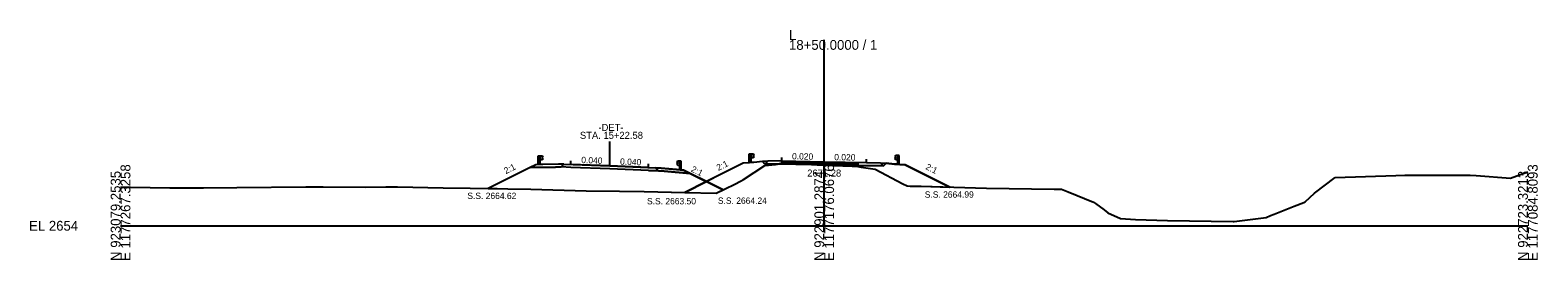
# Model space of a CAD drawing. Extents: x -26 to 1403, y -10 to 9563.
# Drawn here: x -25.7 to 402.8, y 8490.3 to 8555.6 of the extents above; entities that cross this region are included whole.
import ezdxf

# ---------------------------------------------------------------- set-up
doc = ezdxf.new("R2010")
doc.units = 0
for name, color, linetype in [('Exist Cross Section Cell', 7, 'Continuous'), ('Exist XS Center Line Elevation Label', 7, 'Continuous'), ('Exist XS Ground Line', 7, 'Continuous'), ('Prop XS Dump Level', 7, 'Continuous'), ('Prop XS Earthwork Shape', 7, 'Continuous'), ('Prop XS EOT Tick Mark', 7, 'Continuous'), ('Prop XS Finish Grade', 7, 'Continuous'), ('Prop XS Finish Grade Earthwork', 7, 'Continuous'), ('Prop XS Finish Grade Paved Shoulder', 7, 'Continuous'), ('Prop XS Finish Grade Pavement', 7, 'Continuous'), ('Prop XS Guardrail', 7, 'Continuous'), ('Prop XS Pvmt Edge Slope', 7, 'Continuous'), ('Prop XS SE Text', 7, 'Continuous'), ('Prop XS Shoulder Borrow Shape', 7, 'Continuous'), ('Prop XS Side Slope Text', 7, 'Continuous'), ('Prop XS SS Elevation Text', 7, 'Continuous'), ('Prop XS Subgrade Earthwork', 7, 'Continuous'), ('Prop XS Vertical Lines', 7, 'Continuous'), ('Prop XS Wedging', 7, 'Continuous')]:
    doc.layers.add(name, color=color, linetype=linetype)

msp = doc.modelspace()

# ---------------------------------------------------------------- linework, layer by layer
at = {"layer": 'Exist Cross Section Cell'}
for p, q in [((200, 8500), (200, 8552.84)), ((0, 8500), (200, 8500)), ((200, 8500), (400, 8500))]:
    msp.add_line(p, q, dxfattribs=at)
at = {"layer": 'Exist XS Ground Line'}
for p, q in [((177.02, 8513.16), (183.08, 8517.11)), ((183.08, 8517.11), (186.16, 8517.47)), ((186.16, 8517.47), (187.36, 8517.61)), ((187.36, 8517.61), (196.36, 8517.4)), ((196.36, 8517.4), (197.99, 8517.36)), ((197.99, 8517.36), (200, 8517.28)), ((200, 8517.28), (207.95, 8516.94)), ((207.95, 8516.94), (209.54, 8516.86)), ((209.54, 8516.86), (210.55, 8516.7)), ((210.55, 8516.7), (214.49, 8516.09)), ((214.49, 8516.09), (222.34, 8511.97)), ((395.04, 8513.57), (400, 8515.31)), ((0, 8510.95), (2.86, 8510.96)), ((2.86, 8510.96), (14, 8510.78)), ((14, 8510.78), (20.88, 8510.77)), ((20.88, 8510.77), (23.56, 8510.77)), ((23.56, 8510.77), (33.09, 8510.85)), ((33.09, 8510.85), (52.68, 8511.08)), ((52.68, 8511.08), (57.59, 8511.05)), ((57.59, 8511.05), (69.68, 8511.02)), ((69.68, 8511.02), (75.4, 8511.08)), ((75.4, 8511.08), (78.69, 8511.05)), ((78.69, 8511.05), (91.74, 8510.78)), ((91.74, 8510.78), (107.09, 8510.59)), ((172.06, 8510.61), (174.41, 8511.77)), ((174.41, 8511.77), (176.36, 8512.74)), ((176.36, 8512.74), (177.02, 8513.16)), ((222.34, 8511.97), (223.55, 8511.34)), ((223.55, 8511.34), (224.46, 8511.3)), ((224.46, 8511.3), (227.58, 8511.24)), ((227.58, 8511.24), (246.16, 8510.67)), ((246.16, 8510.67), (265.41, 8510.43)), ((339.37, 8509.28), (345.21, 8513.7)), ((345.21, 8513.7), (362.5, 8514.26)), ((362.5, 8514.26), (365, 8514.4)), ((365, 8514.4), (366.49, 8514.42)), ((366.49, 8514.42), (368.44, 8514.4)), ((368.44, 8514.4), (383.21, 8514.39)), ((383.21, 8514.39), (383.56, 8514.41)), ((383.56, 8514.41), (385.3, 8514.27)), ((385.3, 8514.27), (395.04, 8513.57)), ((107.09, 8510.59), (110.11, 8510.53)), ((110.11, 8510.53), (116.65, 8510.37)), ((116.65, 8510.37), (132.38, 8509.95)), ((132.38, 8509.95), (141.79, 8509.85)), ((141.79, 8509.85), (148.87, 8509.72)), ((148.87, 8509.72), (160.51, 8509.5)), ((160.51, 8509.5), (169.34, 8509.29)), ((169.34, 8509.29), (172.06, 8510.61)), ((265.41, 8510.43), (267.42, 8510.41)), ((267.42, 8510.41), (269.38, 8509.61)), ((269.38, 8509.61), (276.55, 8506.7)), ((276.55, 8506.7), (277.08, 8506.34)), ((333.6, 8505.59), (336.33, 8506.66)), ((336.33, 8506.66), (336.67, 8506.85)), ((336.67, 8506.85), (339.37, 8509.28)), ((277.08, 8506.34), (279.58, 8504.49)), ((279.58, 8504.49), (280.64, 8503.71)), ((280.64, 8503.71), (284.18, 8502.04)), ((316.55, 8501.23), (325.62, 8502.34)), ((325.62, 8502.34), (326.88, 8502.92)), ((326.88, 8502.92), (327.85, 8503.29)), ((327.85, 8503.29), (333.6, 8505.59)), ((284.18, 8502.04), (288.48, 8501.79)), ((288.48, 8501.79), (297.54, 8501.54)), ((297.54, 8501.54), (316.22, 8501.22)), ((316.22, 8501.22), (316.55, 8501.23))]:
    msp.add_line(p, q, dxfattribs=at)
at = {"layer": 'Prop XS Dump Level'}
for p, q in [((126.02, 8517.53), (139.03, 8517.01)), ((139.03, 8517.01), (128.02, 8517.45)), ((150.04, 8516.58), (139.03, 8517.01)), ((139.03, 8517.01), (152.04, 8516.5)), ((188, 8518.44), (200, 8518.2)), ((200, 8518.2), (212, 8517.96))]:
    msp.add_line(p, q, dxfattribs=at)
at = {"layer": 'Prop XS Earthwork Shape'}
for p, q in [((116.38, 8516.55), (104.51, 8510.62)), ((123.65, 8516.7), (116.38, 8516.55)), ((125.22, 8516.73), (123.65, 8516.7)), ((128.02, 8516.62), (125.22, 8516.73)), ((139.03, 8516.18), (128.02, 8516.62)), ((150.04, 8515.74), (139.03, 8516.18)), ((152.91, 8515.63), (150.04, 8515.74)), ((154.52, 8515.5), (152.91, 8515.63)), ((161.95, 8514.9), (154.52, 8515.5)), ((177, 8517.8), (166.58, 8512.59)), ((177.02, 8513.16), (183.08, 8517.11)), ((182.43, 8518.24), (180, 8518.04)), ((183.15, 8517.51), (182.43, 8518.24)), ((183.08, 8517.11), (186.16, 8517.47)), ((187.21, 8517.59), (183.15, 8517.51)), ((186.16, 8517.47), (187.21, 8517.59)), ((187.36, 8517.61), (187.21, 8517.59)), ((187.21, 8517.59), (187.69, 8517.6)), ((187.69, 8517.6), (187.36, 8517.61)), ((188, 8517.61), (187.69, 8517.6)), ((187.69, 8517.6), (188, 8517.6)), ((188, 8517.6), (188, 8517.61)), ((216.85, 8517.03), (209.54, 8517.18)), ((209.54, 8517.18), (209.54, 8516.86)), ((209.54, 8516.86), (210.55, 8516.7)), ((210.55, 8516.7), (214.49, 8516.09)), ((214.49, 8516.09), (222.34, 8511.97)), ((217.57, 8517.76), (216.85, 8517.03)), ((220, 8517.56), (217.57, 8517.76)), ((220.82, 8517.5), (220, 8517.56)), ((235.67, 8510.99), (223, 8517.32)), ((160.39, 8509.5), (166.58, 8512.59)), ((166.58, 8512.59), (160.39, 8509.5)), ((166.58, 8512.59), (160.39, 8509.5)), ((166.58, 8512.59), (161.95, 8514.9)), ((171.29, 8510.24), (166.58, 8512.59)), ((171.29, 8510.24), (166.58, 8512.59)), ((166.58, 8512.59), (171.29, 8510.24)), ((172.06, 8510.61), (174.41, 8511.77)), ((174.41, 8511.77), (176.36, 8512.74)), ((176.36, 8512.74), (177.02, 8513.16)), ((222.34, 8511.97), (223.55, 8511.34)), ((223.55, 8511.34), (224.46, 8511.3)), ((224.46, 8511.3), (227.58, 8511.24)), ((227.58, 8511.24), (235.67, 8510.99)), ((104.51, 8510.62), (107.09, 8510.59)), ((107.09, 8510.59), (110.11, 8510.53)), ((110.11, 8510.53), (116.65, 8510.37)), ((116.65, 8510.37), (132.38, 8509.95)), ((132.38, 8509.95), (141.79, 8509.85)), ((141.79, 8509.85), (148.87, 8509.72)), ((148.87, 8509.72), (160.39, 8509.5)), ((160.39, 8509.5), (160.51, 8509.5)), ((160.39, 8509.5), (160.51, 8509.5)), ((160.51, 8509.5), (169.34, 8509.29)), ((160.51, 8509.5), (169.34, 8509.29)), ((169.34, 8509.29), (171.29, 8510.24)), ((169.34, 8509.29), (171.29, 8510.24)), ((171.29, 8510.24), (172.06, 8510.61))]:
    msp.add_line(p, q, dxfattribs=at)
for points in [[(180, 8518.04), (179.18, 8517.98), (178.68, 8517.94), (177, 8517.8)], [(223, 8517.32), (221.32, 8517.46), (220.82, 8517.5)]]:
    msp.add_lwpolyline(points, dxfattribs=at)
at = {"layer": 'Prop XS EOT Tick Mark'}
for p, q in [((188, 8518.44), (188, 8519.44)), ((128.02, 8517.45), (128.02, 8518.45)), ((150.04, 8516.58), (150.04, 8517.58)), ((212, 8517.96), (212, 8518.96))]:
    msp.add_line(p, q, dxfattribs=at)
at = {"layer": 'Prop XS Finish Grade'}
for p, q in [((126.02, 8517.53), (124.45, 8517.5)), ((152.04, 8516.5), (153.65, 8516.37)), ((184, 8518.36), (182.43, 8518.24)), ((216, 8517.88), (217.57, 8517.76))]:
    msp.add_line(p, q, dxfattribs=at)
at = {"layer": 'Prop XS Finish Grade Earthwork'}
for p, q in [((116.38, 8516.55), (104.51, 8510.62)), ((118.02, 8517.37), (116.38, 8516.55)), ((120.02, 8517.41), (118.02, 8517.37)), ((124.45, 8517.5), (120.02, 8517.41)), ((153.65, 8516.37), (158.05, 8516.02)), ((158.05, 8516.02), (160.05, 8515.86)), ((160.05, 8515.86), (161.95, 8514.9)), ((177, 8517.8), (160.39, 8509.5)), ((180, 8518.04), (177, 8517.8)), ((182.43, 8518.24), (180, 8518.04)), ((217.57, 8517.76), (220, 8517.56)), ((220, 8517.56), (223, 8517.32)), ((223, 8517.32), (235.67, 8510.99)), ((161.95, 8514.9), (171.29, 8510.24))]:
    msp.add_line(p, q, dxfattribs=at)
at = {"layer": 'Prop XS Finish Grade Paved Shoulder'}
for p, q in [((188, 8518.44), (184, 8518.36)), ((212, 8517.96), (216, 8517.88))]:
    msp.add_line(p, q, dxfattribs=at)
at = {"layer": 'Prop XS Finish Grade Pavement'}
for p, q in [((126.02, 8517.53), (139.03, 8517.01)), ((139.03, 8517.01), (152.04, 8516.5)), ((188, 8518.44), (200, 8518.2)), ((200, 8518.2), (212, 8517.96))]:
    msp.add_line(p, q, dxfattribs=at)
at = {"layer": 'Prop XS Guardrail'}
for p, q in [((118.7, 8519.88), (119.2, 8519.88)), ((118.7, 8517.38), (118.7, 8519.88)), ((119.2, 8519.88), (119.7, 8519.88)), ((119.2, 8519.88), (119.2, 8517.38)), ((119.7, 8519.88), (119.99, 8519.68)), ((119.99, 8519.56), (119.7, 8519.36)), ((119.7, 8519.36), (119.7, 8519.27)), ((119.7, 8519.27), (119.99, 8519.07)), ((119.99, 8519.68), (120.02, 8519.62)), ((120.02, 8519.62), (119.99, 8519.56)), ((178.68, 8520.44), (179.18, 8520.44)), ((178.68, 8517.94), (178.68, 8520.44)), ((179.18, 8520.44), (179.68, 8520.44)), ((179.18, 8520.44), (179.18, 8517.94)), ((179.68, 8519.3), (179.18, 8519.3)), ((179.68, 8520.44), (179.97, 8520.24)), ((179.97, 8520.12), (179.68, 8519.92)), ((179.68, 8519.92), (179.68, 8519.82)), ((179.68, 8519.82), (179.97, 8519.62)), ((179.97, 8519.5), (179.68, 8519.3)), ((179.97, 8520.24), (180, 8520.18)), ((180, 8520.18), (179.97, 8520.12)), ((179.97, 8519.62), (180, 8519.56)), ((180, 8519.56), (179.97, 8519.5)), ((220.03, 8519.76), (220, 8519.7)), ((220, 8519.7), (220.03, 8519.64)), ((220.32, 8519.96), (220.03, 8519.76)), ((220.03, 8519.64), (220.32, 8519.44)), ((220.32, 8519.34), (220.03, 8519.14)), ((220.82, 8519.96), (220.32, 8519.96)), ((220.32, 8519.44), (220.32, 8519.34)), ((221.32, 8519.96), (220.82, 8519.96)), ((220.82, 8519.96), (220.82, 8517.46)), ((221.32, 8517.46), (221.32, 8519.96)), ((119.7, 8518.75), (119.2, 8518.75)), ((119.99, 8518.95), (119.7, 8518.75)), ((119.99, 8519.07), (120.02, 8519.01)), ((120.02, 8519.01), (119.99, 8518.95)), ((158.07, 8518.21), (158.04, 8518.15)), ((158.04, 8518.15), (158.07, 8518.09)), ((158.07, 8517.6), (158.04, 8517.54)), ((158.04, 8517.54), (158.07, 8517.48)), ((158.36, 8518.41), (158.07, 8518.21)), ((158.07, 8518.09), (158.36, 8517.89)), ((158.36, 8517.8), (158.07, 8517.6)), ((158.07, 8517.48), (158.36, 8517.28)), ((158.86, 8518.41), (158.36, 8518.41)), ((158.36, 8517.89), (158.36, 8517.8)), ((158.36, 8517.28), (158.86, 8517.28)), ((159.36, 8518.41), (158.86, 8518.41)), ((158.86, 8518.41), (158.86, 8515.91)), ((159.36, 8515.91), (159.36, 8518.41)), ((220.03, 8519.14), (220, 8519.08)), ((220, 8519.08), (220.03, 8519.02)), ((220.03, 8519.02), (220.32, 8518.82)), ((220.32, 8518.82), (220.82, 8518.82))]:
    msp.add_line(p, q, dxfattribs=at)
at = {"layer": 'Prop XS Pvmt Edge Slope'}
for p, q in [((126.02, 8517.53), (125.22, 8516.73)), ((152.04, 8516.5), (152.91, 8515.63)), ((184, 8518.36), (183.15, 8517.51)), ((216, 8517.88), (216.85, 8517.03))]:
    msp.add_line(p, q, dxfattribs=at)
at = {"layer": 'Prop XS Shoulder Borrow Shape'}
for p, q in [((118.02, 8517.37), (116.38, 8516.55)), ((116.38, 8516.55), (123.65, 8516.7)), ((124.45, 8517.5), (120.02, 8517.41)), ((123.65, 8516.7), (125.22, 8516.73)), ((126.02, 8517.53), (124.45, 8517.5)), ((125.22, 8516.73), (126.02, 8517.53)), ((153.65, 8516.37), (152.04, 8516.5)), ((152.04, 8516.5), (152.91, 8515.63)), ((152.91, 8515.63), (154.52, 8515.5)), ((158.05, 8516.02), (153.65, 8516.37)), ((154.52, 8515.5), (161.95, 8514.9)), ((160.05, 8515.86), (159.36, 8515.91)), ((159.36, 8515.91), (159.36, 8515.91)), ((161.95, 8514.9), (160.05, 8515.86))]:
    msp.add_line(p, q, dxfattribs=at)
for points in [[(120.02, 8517.41), (119.2, 8517.39), (118.7, 8517.38), (118.02, 8517.37)], [(159.36, 8515.91), (158.86, 8515.95), (158.05, 8516.02)], [(159.36, 8515.91), (159.36, 8515.91)]]:
    msp.add_lwpolyline(points, dxfattribs=at)
at = {"layer": 'Prop XS Subgrade Earthwork'}
for p, q in [((123.65, 8516.7), (116.38, 8516.55)), ((125.22, 8516.73), (123.65, 8516.7)), ((128.02, 8516.62), (125.22, 8516.73)), ((139.03, 8516.18), (128.02, 8516.62)), ((150.04, 8515.74), (139.03, 8516.18)), ((150.04, 8515.74), (152.91, 8515.63)), ((152.91, 8515.63), (154.52, 8515.5)), ((154.52, 8515.5), (161.95, 8514.9)), ((183.15, 8517.51), (182.43, 8518.24)), ((188, 8517.61), (183.15, 8517.51)), ((188, 8517.6), (188, 8517.61)), ((209.54, 8517.18), (209.54, 8516.86)), ((209.54, 8517.18), (216.85, 8517.03)), ((216.85, 8517.03), (217.57, 8517.76))]:
    msp.add_line(p, q, dxfattribs=at)
at = {"layer": 'Prop XS Vertical Lines'}
msp.add_line((139.03, 8517.01), (139.03, 8524.01), dxfattribs=at)
at = {"layer": 'Prop XS Wedging'}
for points in [[(188, 8517.6), (188, 8518.19), (196.36, 8518.03), (197.99, 8517.99), (200, 8517.95), (207.95, 8517.79), (209.54, 8517.76), (209.54, 8516.86), (207.95, 8516.94), (200, 8517.28), (197.99, 8517.36), (196.36, 8517.4)], [(188, 8517.6), (188, 8518.19), (196.36, 8518.03), (197.99, 8517.99), (200, 8517.95), (207.95, 8517.79), (209.54, 8517.76), (209.54, 8516.86), (207.95, 8516.94), (200, 8517.28), (197.99, 8517.36), (196.36, 8517.4)], [(188, 8517.6), (188, 8517.94), (196.36, 8517.78), (197.99, 8517.74), (200, 8517.7), (207.95, 8517.54), (209.54, 8517.51), (209.54, 8516.86), (207.95, 8516.94), (200, 8517.28), (197.99, 8517.36), (196.36, 8517.4)]]:
    msp.add_lwpolyline(points, close=True, dxfattribs=at)

# ---------------------------------------------------------------- texts
at = {"layer": 'Exist Cross Section Cell'}
for s, p in [('L', (190, 8552.84)), ('18+50.0000 / 1', (190, 8550.04)), ('EL 2654', (-26, 8498.6))]:
    msp.add_text(s, height=2.8, dxfattribs=at).set_placement(p)
for s, p in [('N 923079.2535', (0, 8490)), ('E 1177267.3258', (2.8, 8490)), ('N 922901.2874', (200, 8490)), ('E 1177176.0676', (202.8, 8490)), ('N 922723.3213', (400, 8490)), ('E 1177084.8093', (402.8, 8490))]:
    msp.add_text(s, height=2.8, rotation=90, dxfattribs=at).set_placement(p)
at = {"layer": 'Exist XS Center Line Elevation Label'}
msp.add_text('2671.28', height=2, dxfattribs=at).set_placement((195.17, 8513.99))
at = {"layer": 'Prop XS Dump Level'}
for s, p in [('Case1', (120.02, 8517.37)), ('Case1', (157.79, 8515.62)), ('Case2', (180, 8518)), ('Case2', (220, 8517.52))]:
    msp.add_text(s, height=0.04, dxfattribs=at).set_placement(p)
at = {"layer": 'Prop XS SE Text'}
for s, rotation, p in [('0.040', 357.7209, (130.93, 8517.84)), ('0.020', 358.8542, (190.84, 8518.89)), ('0.020', 358.8542, (202.84, 8518.65)), ('0.040', 357.7212, (141.95, 8517.4))]:
    msp.add_text(s, height=1.8, rotation=rotation, dxfattribs=at).set_placement(p)
at = {"layer": 'Prop XS Side Slope Text'}
for rotation, p in [(26.5651, (109.51, 8514.67)), (333.4349, (161.97, 8515.51)), (26.5651, (169.92, 8515.57)), (333.4349, (228.65, 8516.18))]:
    msp.add_text('2:1', height=1.8, rotation=rotation, dxfattribs=at).set_placement(p)
at = {"layer": 'Prop XS SS Elevation Text'}
for s, p in [('S.S. 2664.62', (98.58, 8507.62)), ('S.S. 2663.50', (149.64, 8506.09)), ('S.S. 2664.24', (169.78, 8506.24)), ('S.S. 2664.99', (228.59, 8507.99))]:
    msp.add_text(s, height=1.8, dxfattribs=at).set_placement(p)
at = {"layer": 'Prop XS Vertical Lines'}
for s, p in [('-DET-', (135.83, 8526.97)), ('STA. 15+22.58', (130.57, 8524.72))]:
    msp.add_text(s, height=2, dxfattribs=at).set_placement(p)

doc.saveas('drawing.dxf')
